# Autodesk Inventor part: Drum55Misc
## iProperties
Author: Rich
Shininess: 21.0
Angle Display Precision: 2
Document Length Units: 11272
Document Angle Units: 11286
Document Time Units: 11279
Document Mass Units: 11290
Document Length Units Precision: 3
Document Angle Units Precision: 2
Compacted: True
PropertySet Name: _Private Model Information
Created: 2001-12
Part Number: Drum55Misc
Document SubType Name: Modeling
Designer: Rich
Control State: 0
Master: False
Checked Out: False
PropertySet Name: Design Tracking Control
Density: 0.0
Volumn: 0.0
Area: 0.0
PropertySet Name: Model Information
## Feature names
1. Revolution1
2. Shell2
3. Revolution2
